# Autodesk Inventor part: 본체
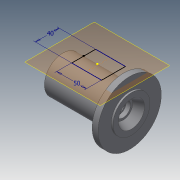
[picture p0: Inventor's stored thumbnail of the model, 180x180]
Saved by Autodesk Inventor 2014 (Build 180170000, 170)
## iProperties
Created: 2017-05
Part Number: 본체
Material: 일반
Document SubType Name: Modeling
Designer: user
Density: 1 g/cm^3
Appearance: 기본값
Author: user
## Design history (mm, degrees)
sketch "스케치1"
  geometry: L1 (-57.5, 0)-(57.5, 0); L2 (-57.5, 0)-(-57.5, 31); L3 (-57.5, 31)-(44.5, 31); L4 (44.5, 31)-(44.5, 53); L5 (44.5, 53)-(54.5, 53); L6 (54.5, 53)-(54.5, 31); L7 (54.5, 31)-(57.5, 31); L8 (57.5, 31)-(57.5, 0); 2 further points
  constraints: 16 end point, 3 parallel, 3 perpendicular, 1 coincident, 1 collinear, 1 horizontal, 1 midpoint
  dimensions: "d0" = 115 distance of L1.start L1.end; "d1" = 62 diameter of L3 L1; "d2" = 106 diameter of L5 L1; "d3" = 62 diameter of L7 L1; "d4" = 3 distance of L6.end L7.end; "d5" = 13 distance between parallel lines of L4 L8
revolve "회전1" sketch "스케치1" stored, may be unused: angle "d6" = 90 deg
sketch "스케치2"
  geometry: L1 (-57.5, -31)-(-57.5, 31) reference; L2 (-57.5, 31)-(44.5, 31) reference; L3 (44.5, 31)-(44.5, 53) reference; L4 (44.5, 53)-(54.5, 53) reference; L5 (54.5, 53)-(54.5, 31) reference; L6 (54.5, 31)-(57.5, 31) reference; L7 (57.5, 31)-(57.5, -31) reference; L8 (57.5, -31)-(54.5, -31) reference; L9 (54.5, -31)-(54.5, -53) reference; L10 (54.5, -53)-(44.5, -53) reference; L11 (44.5, -53)-(44.5, -31) reference; L12 (44.5, -31)-(-57.5, -31) reference; L13 (-57.5, 0)-(-48.5, 0); L14 (-48.5, 0)-(-48.5, 21); L15 (-48.5, 21)-(-57.5, 21); L16 (-57.5, 21)-(-57.5, 0); L17 (-48.5, 0)-(-45.5, 0); L18 (-45.5, 0)-(-45.5, 24); L19 (-45.5, 24)-(-48.5, 24); L20 (-48.5, 24)-(-48.5, 0); L21 (-45.5, 0)-(-36.5, 0); L22 (-36.5, 0)-(-36.5, 20); L23 (-36.5, 20)-(-45.5, 20); L24 (-45.5, 20)-(-45.5, 0); L25 (-36.5, 0)-(-33.25, 0); L26 (-33.25, 0)-(-33.25, 17.5); L27 (-33.25, 17.5)-(-36.5, 17.5); L28 (-36.5, 17.5)-(-36.5, 0); L29 (-33.25, 0)-(-31.5, 0); L30 (-31.5, 0)-(-31.5, 18.5); L31 (-31.5, 18.5)-(-33.25, 18.5); L32 (-33.25, 18.5)-(-33.25, 0); L33 (-31.5, 0)-(-20.5, 0); L34 (-20.5, 0)-(-20.5, 17.5); L35 (-20.5, 17.5)-(-31.5, 17.5); L36 (-31.5, 17.5)-(-31.5, 0); L37 (-20.5, 0)-(17.5, 0); L38 (17.5, 0)-(17.5, 26); L39 (17.5, 26)-(-20.5, 26); L40 (-20.5, 26)-(-20.5, 0); L41 (17.5, 0)-(28.5, 0); L42 (28.5, 0)-(28.5, 17.5); L43 (28.5, 17.5)-(17.5, 17.5); L44 (17.5, 17.5)-(17.5, 0); L45 (28.5, 0)-(33.5, 0); L46 (33.5, 0)-(33.5, 13.5); L47 (30.5, 16.5)-(28.5, 16.5); L48 (28.5, 16.5)-(28.5, 0); L49 (33.5, 0)-(36.2, 0); L50 (36.2, 0)-(36.2, 10); L51 (36.2, 10)-(33.5, 10); L52 (33.5, 10)-(33.5, 0); L53 (36.2, 0)-(43.5, 0); L54 (43.5, 0)-(43.5, 12.5); L55 (43.5, 12.5)-(36.2, 12.5); L56 (36.2, 12.5)-(36.2, 0); L57 (43.5, 0)-(43.5, 16); L58 (43.5, 16)-(57.5, 22); L59 (57.5, 0)-(43.5, 0); L60 (57.5, 22)-(57.5, 0); A1 r 3 centre (30.5, 13.5) between (33.5, 13.5) and (30.5, 16.5); 1 further point
  constraints: 96 end point, 23 parallel, 11 horizontal, 11 perpendicular, 4 collinear, 2 midpoint, 2 point on circle, 2 tangent, 1 centre point, 1 point on line
  dimensions: "d7" = 44 diameter of L58.end L59; "d8" = 32 diameter of L57.end L59; "d9" = 25 diameter of L55 L59; "d10" = 20 diameter of L51 L59; "d11" = 33 diameter of L47 L59; "d12" = 35 diameter of L43 L59; "d13" = 52 diameter of L39 L59; "d14" = 37 diameter of L31 L59; "d15" = 40 diameter of L23 L59; "d16" = 48 diameter of L19 L59; "d17" = 42 diameter of L15 L59; "d18" = 12 distance between parallel lines of L24 L1; "d19" = 3 distance of L18.end L19.end; "d20" = 21 distance between parallel lines of L22 L16; "d21" = 26 distance between parallel lines of L30 L1; "d22" = 1.75 distance of L30.end L31.end; "d23" = 60 distance between parallel lines of L42 L30; "d24" = 14 distance between parallel lines of L57 L60; "d25" = 24 distance between parallel lines of L46 L7; "d26" = 38 distance of L38.end L39.end; "d27" = 11 distance of L42.end L43.end; "d28" = 7.3 distance of L54.end L55.end; "d29" = 3 radius of A1
revolve "회전2" sketch "스케치2" stored, may be unused: angle "d30" = 90 deg
node "작업 평면1"
sketch "스케치3"
  geometry: L1 (22.903, -20)-(-27.097, -20); L2 (-27.097, -20)-(-27.097, 20); L3 (-27.097, 20)-(22.903, 20); L4 (22.903, 20)-(22.903, -20); L5 (-2.097, -20)-(-2.097, 20); 2 further points
  constraints: 10 end point, 3 midpoint, 2 parallel, 1 horizontal, 1 horizontal alignment, 1 perpendicular
  dimensions: "d32" = 50 distance of L2.end L3.end; "d33" = 40 distance of L3.end L1.start
node "솔리드1"
node "절단 모서리 투영1"
other parameters: "d31" = 44
